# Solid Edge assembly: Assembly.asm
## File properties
Author: Administrator
Template: Normal.asm
Last saved by: CADCIM
Revision: 7
Application: Solid Edge
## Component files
Stock_support_base.par
thrust_bearing.par
adjusting_screw_nut.par
support_adjusting_screw.par
support_roller_bracket.par
stock_support_roller.par
adjusting_nut_handle.par
adjusting_screw_guide.par
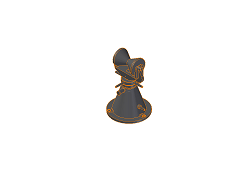
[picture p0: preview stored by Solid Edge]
